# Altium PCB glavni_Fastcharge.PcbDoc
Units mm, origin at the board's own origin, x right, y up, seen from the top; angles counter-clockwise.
Board outline 90.02 x 90.02 mm, 2 copper layers (Top Layer, Bottom Layer); 0 components, 0 nets, 77 pads, 2 vias.
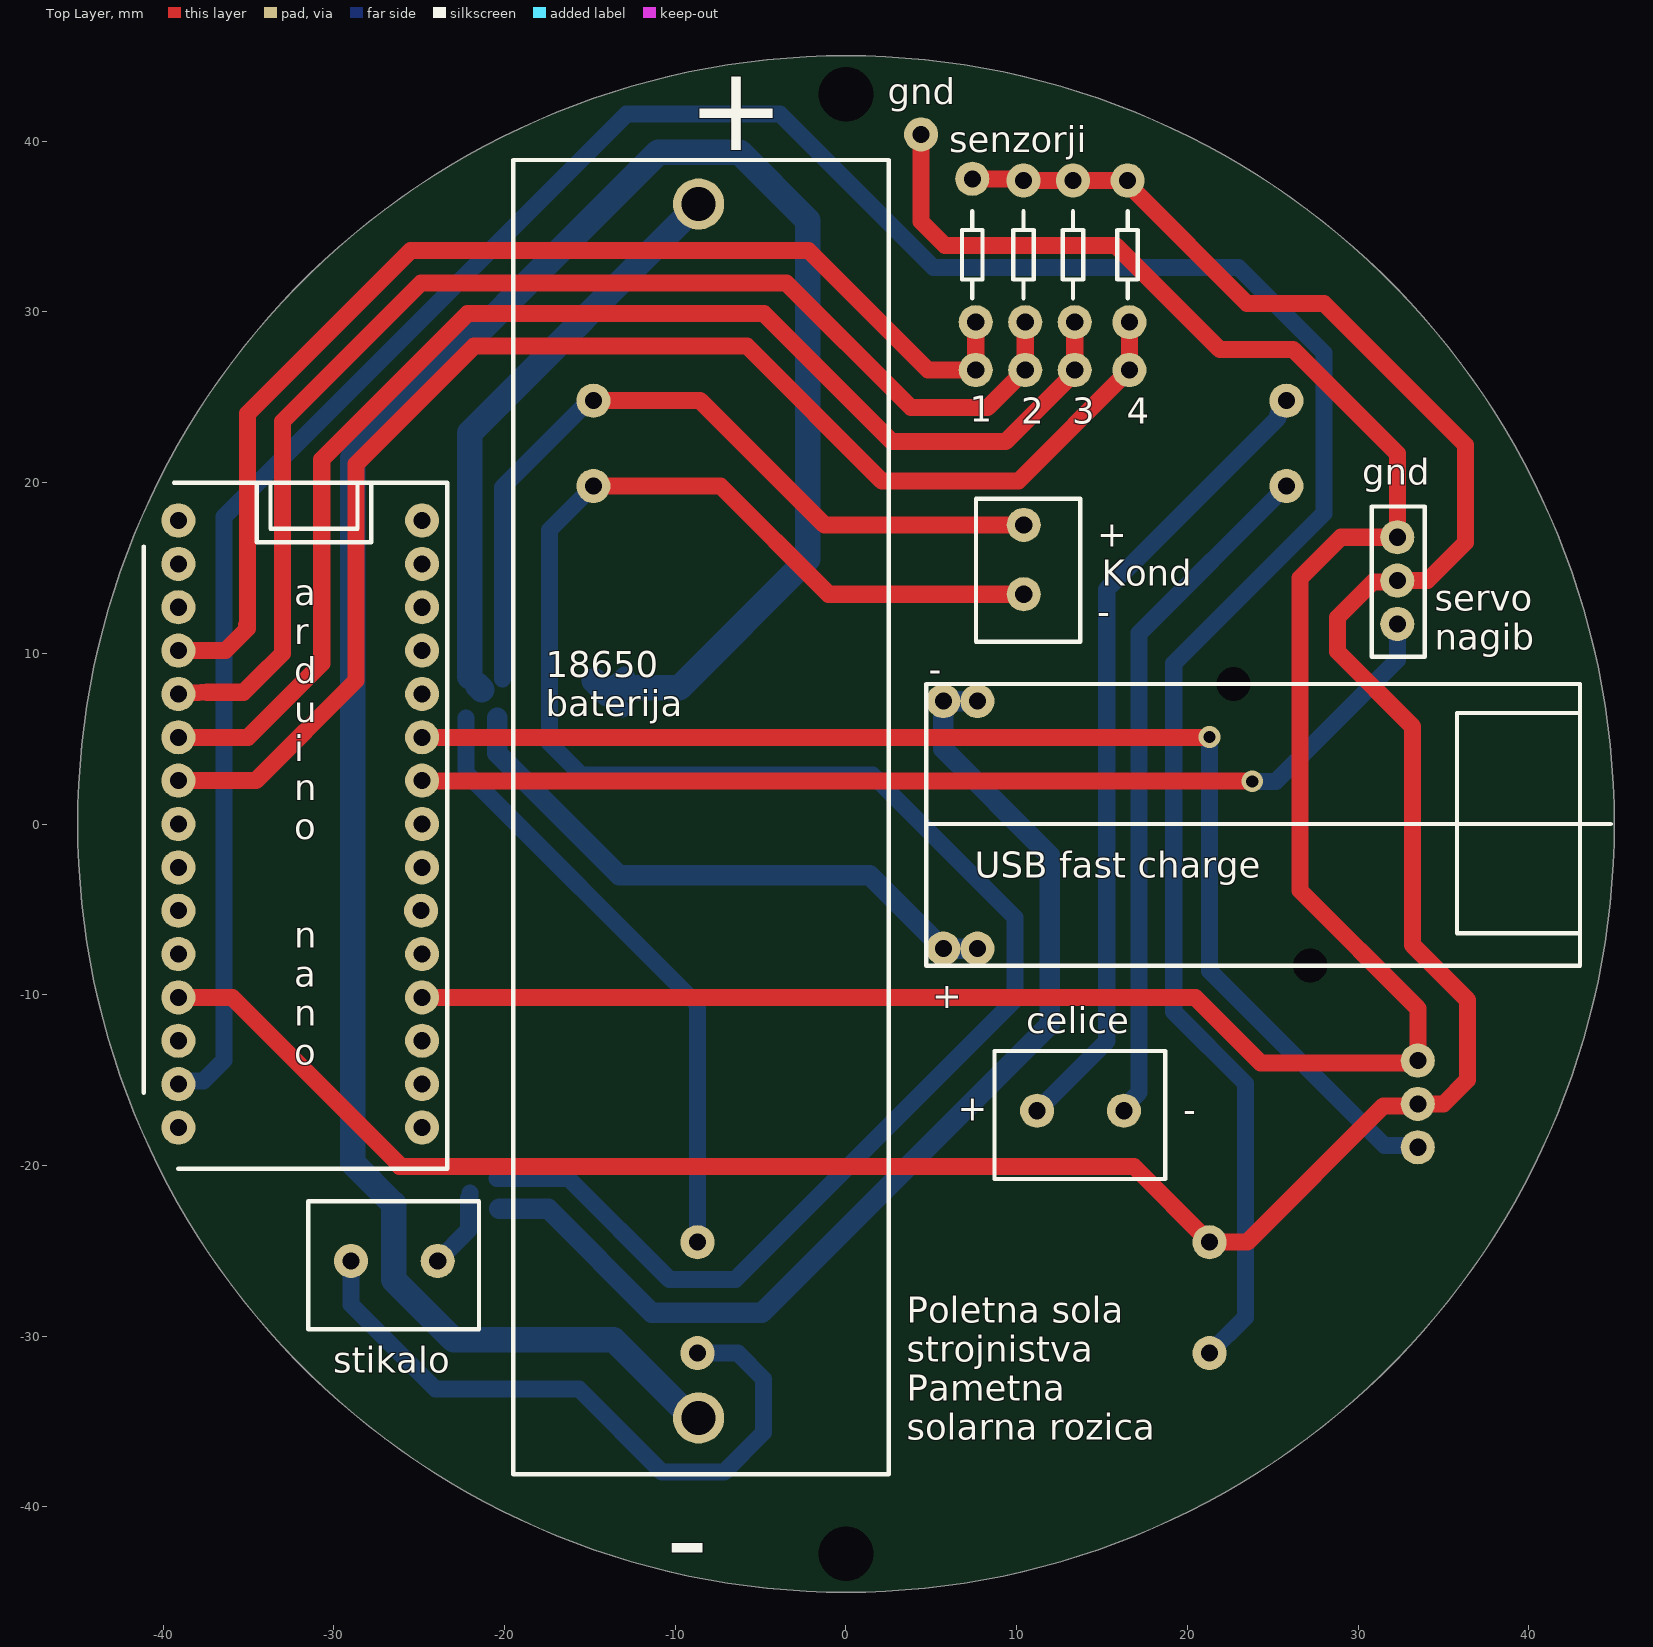
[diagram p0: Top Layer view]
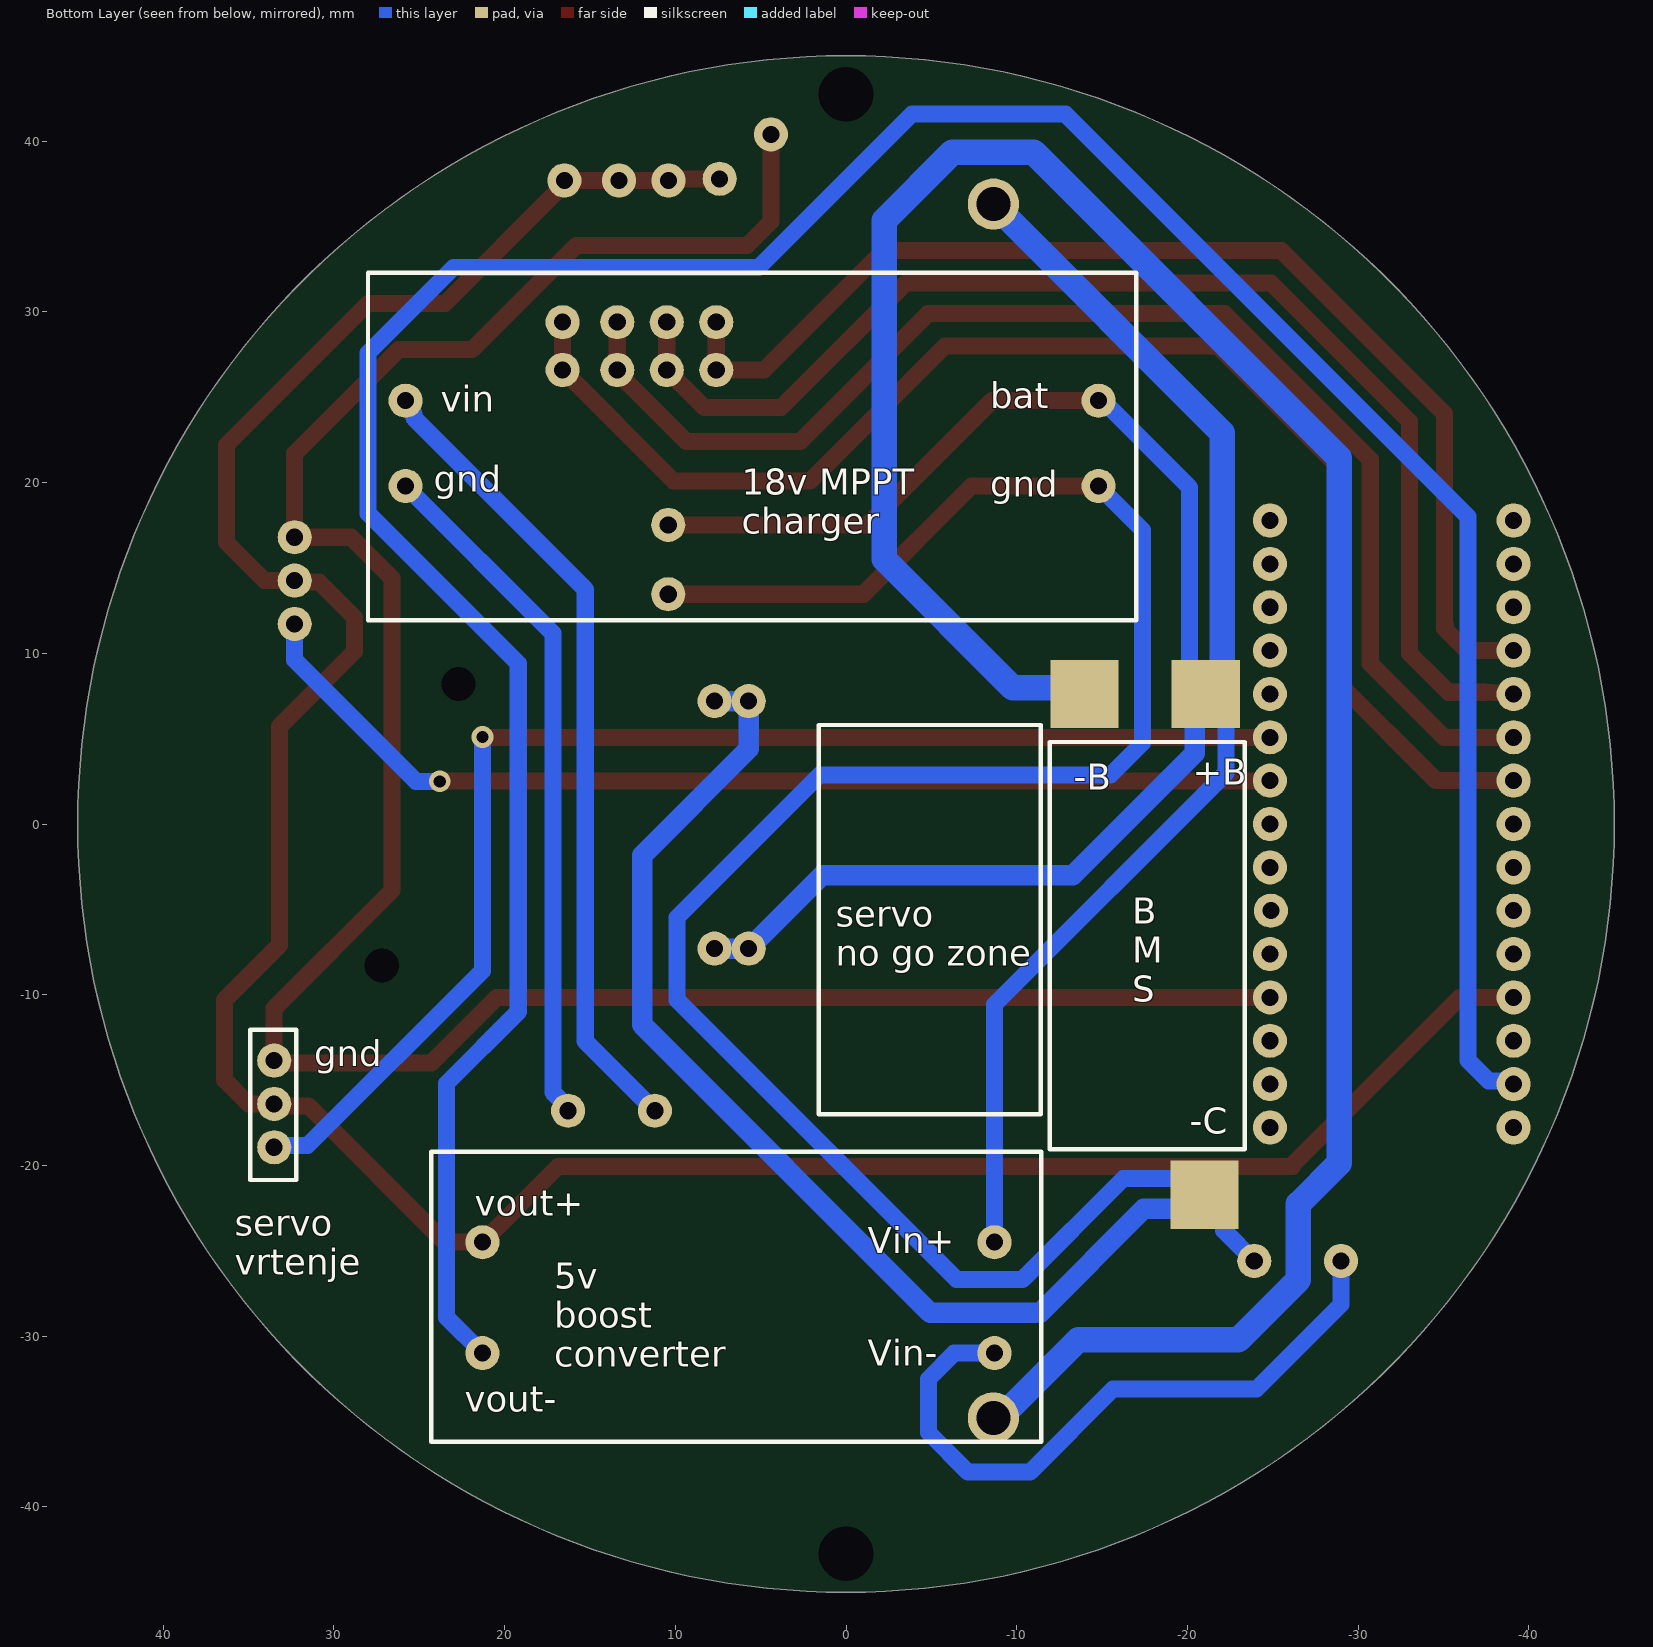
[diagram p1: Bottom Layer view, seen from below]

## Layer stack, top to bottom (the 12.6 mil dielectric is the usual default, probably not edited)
Top Solder: solder mask 0.0102, Solder Resist, Dk 3.5
Top Layer: signal copper 0.0356
Dielectric 1: dielectric 0.32, FR-4, Dk 4.8
Bottom Layer: signal copper 0.0356
Bottom Solder: solder mask 0.0102, Solder Resist, Dk 3.5

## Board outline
-45.011,0 ccw(c0,0) 0,-45.011 ccw(c0,0) 45.011,0 ccw(c0,0) 0,45.011 ccw(c0,0)

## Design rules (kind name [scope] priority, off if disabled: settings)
Clearance [All] p1: gap=0.254 ignorepadtopadclearanceinfootprint=FALSE except(0: Arc-Hole Track-Hole SMDPad-Hole THPad-Hole Via-Hole Fill-Hole Poly-Hole Region-Hole Text-Hole)
PolygonConnect [All] p1: connectstyle=Relief reliefconductorwidth=0.254 reliefentries=4 polygonreliefangle="90 Angle" airgapwidth=0.254
RoutingVias [All] p1: holewidth=0.711 width=1.27 viastyle="Through Hole" minholewidth=0.711 minwidth=1.27 maxholewidth=0.711 maxwidth=1.27
SolderMaskExpansion [All] p1: expansion=0.102 istentingtop=FALSE
Width [All] p1: maxlimit=1.5 minlimit=0.5 preferedwidth=1
30 further rules are at their usual default settings.

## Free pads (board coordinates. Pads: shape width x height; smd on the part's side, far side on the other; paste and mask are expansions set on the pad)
  round 2 hole 1: 105(-29,-25.6) 105(11.2,-16.8) 107(-23.92,-25.6) 107(16.28,-16.8) 129(25.8,24.8) 130(25.8,19.8) 131(-14.8,24.8) 132(-14.8,19.8) 137(-8.7,-24.5) 137(21.3,-24.5) 138(-8.7,-31) 138(21.3,-31) 141(-39.116,15.24) 141(-39.116,17.78) 141(-24.892,-5.08) 141(-24.836,-17.78) 141(-24.836,-15.24) 141(-24.836,-12.7) 141(-24.836,-10.16) 141(-24.836,-7.62) 141(-24.836,-2.54) 141(-24.836,0) 141(-24.836,2.54) 141(-24.836,5.08) 141(-24.836,7.62) 141(-24.836,10.16) 141(-24.836,12.7) 141(-24.836,15.24) 141(-24.836,17.78) 142(-39.116,12.7) 143(-39.116,10.16) 143(32.3,16.8) 143(33.5,-13.86) 144(-39.116,7.62) 144(32.3,14.26) 144(33.5,-16.4) 145(-39.116,5.08) 145(32.3,11.72) 145(33.5,-18.94) 146(-39.116,2.54) 147(-39.116,0) 148(-39.116,-2.54) 149(-39.116,-5.08) 150(-39.116,-7.62) 151(-39.116,-10.16) 152(-39.116,-12.7) 153(-39.116,-15.24) 154(-39.116,-17.78) 155(4.4,40.4) 156(7.6,26.6) 156(10.5,26.6) 156(13.4,26.6) 156(16.6,26.6) 157(7.6,29.4) 157(10.5,29.4) 157(13.4,29.4) 157(16.6,29.4) 158(7.4,37.8) 158(10.4,37.7) 158(10.414,13.462) 158(10.414,17.526) 158(13.3,37.7) 158(16.5,37.7) 169(5.7,-7.3) 169(5.7,7.2) 170(7.7,-7.3) 170(7.7,7.2)
  round 3 hole 2: 128(-8.636,36.322) ""(-8.636,-34.798)
  rect 4x4 smd far side: 134(-21.082,7.62) 134(-21,-21.725) 134(-13.97,7.62)
  round 1.524 hole 0.762: 141(-24.892,-5.08)
  round 2 hole 3.2: 155(0,-42.75) 155(0,42.75)
  round 1.524 hole 2: 171(27.2,-8.3) 172(22.7,8.2)

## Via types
v1: diameter 1.27, hole 0.711, Top Layer to Bottom Layer, 2 vias

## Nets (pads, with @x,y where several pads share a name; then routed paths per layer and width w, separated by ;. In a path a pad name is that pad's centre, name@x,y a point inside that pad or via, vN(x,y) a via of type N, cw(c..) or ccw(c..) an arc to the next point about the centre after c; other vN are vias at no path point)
copper on no net: | length 1541.1
  Top Layer w1: -39.116,-10.16 -35.956,-10.16 -26.116,-20 ; -39.116,2.54 -34.576,2.54 -28.702,8.414 -28.702,21.082 -21.784,28 -5.8,28 2.1,20.1 10.1,20.1 16.6,26.6 16.6,29.7 ; -39.116,5.08 -35.036,5.08 -30.716,9.4 -30.716,21.354 -22.17,29.9 -4.8,29.9 2.7,22.4 9.342,22.4 13.4,26.458 13.4,26.6 13.4,29.4 ; -39.116,7.62 -37.436,7.72 -35.296,7.72 -34.516,8.5 -33.02,9.996 -33.02,23.58 -24.9,31.7 -3.5,31.7 3.6,24.6 3.8,24.4 8.3,24.4 10.5,26.6 10.5,29.7 ; -39.116,10.16 -37.527,10.169 -36.347,10.169 -35.116,11.4 -35.116,11.646 ; -35.052,11.458 -35.052,24.048 -25.5,33.6 -2.2,33.6 4.8,26.6 7.6,26.6 7.6,29.4 ; -26.162,-20.066 16.866,-20.066 21.3,-24.5 23.506,-24.5 31.496,-16.51 33.782,-16.51 ; -24.836,2.54 -24.816,2.52 ; -23.82,-10.16 20.46,-10.16 24.3,-14 33.36,-14 33.5,-13.86 33.5,-10.8 26.6,-3.9 26.6,14.4 29,16.8 32.3,16.8 32.3,21.7 26.2,27.8 21.9,27.8 21.2,28.5 15.8,33.9 5.8,33.9 4.4,35.3 4.4,40.4 ; -23.82,5.08 21.28,5.08 v1(21.3,5.1) ; -23.8,2.52 23.78,2.52 v1(23.8,2.5) ; -14.8,19.8 -7.354,19.8 -1.016,13.462 10.414,13.462 ; -14.8,24.8 -8.544,24.8 -1.27,17.526 10.414,17.526 ; 7.4,29.3 7.6,29.1 ; 7.4,37.8 10.3,37.8 10.4,37.7 13.3,37.7 16.5,37.7 ; 13.2,29.3 13.4,29.1 ; 16.78,37.22 23.5,30.5 28,30.5 36.3,22.2 36.3,20.8 36.3,16.488 34.072,14.26 32.3,14.26 32.221,14.181 30.881,14.181 28.8,12.1 28.8,10.1 33.2,5.7 33.2,-7.1 36.4,-10.3 36.4,-15 35,-16.4 33.5,-16.4
  Bottom Layer w1: -39.116,-15.24 -38.925,-15.049 -37.655,-15.049 -36.449,-13.843 -36.449,-13.664 -36.449,18.001 -12.85,41.6 -3.875,41.6 5.125,32.6 23,32.6 28,27.6 28,18.2 19.2,9.4 19.2,-11 23.4,-15.2 23.4,-28.9 21.3,-31 ; -28.999,-25.601 -28.999,-28.151 -24.05,-33.1 -15.65,-33.1 -10.775,-37.975 -7.15,-37.975 -4.826,-35.651 -4.826,-32.512 -6.338,-31 -8.7,-31 ; -23.92,-25.6 -22.125,-23.805 -22.125,-21.925 -22.025,-21.825 -22.025,-21.625 ; -22.275,6.2 -22.275,3 -8.7,-10.575 -8.7,-12.3 -8.7,-24.5 ; -20.45,-20.775 -16.25,-20.775 -10.35,-26.675 -6.475,-26.675 9.9,-10.3 9.9,-5.475 1.55,2.875 -15.5,2.875 -17.375,4.75 -17.375,17.225 -14.85,19.75 -14.8,19.8 ; -20.125,8.5 -20.125,19.725 -15.05,24.8 -14.8,24.8 ; -13.97,7.62 -13.088,6.738 ; 11.2,-16.8 15.275,-12.725 15.275,13.751 25.3,23.776 25.3,24.029 25.8,24.529 25.8,24.8 ; 16.28,-16.8 16.28,-16.609 17.175,-15.714 17.175,11.175 25.8,19.8 ; v1(21.3,5.1) 21.3,-8.6 31.543,-18.843 33.403,-18.843 33.5,-18.94 ; v1(23.8,2.5) 25.2,2.5 32.3,9.6 32.3,11.72
  Bottom Layer w1.2: -20.425,6.225 -20.425,4.15 -13.275,-3 1.4,-3 5.7,-7.3 7.7,-7.3 ; -20.325,-22.55 -17.45,-22.55 -11.375,-28.625 -4.925,-28.625 11.925,-11.775 11.925,-1.825 5.7,4.4 5.7,7.2 7.7,7.2 ; -13.97,7.62 -12.954,8.636
  Bottom Layer w1.5: -22.05,8.625 -22.05,22.908 -8.636,36.322 ; -21.575,8.113 -21.336,7.874 ; -14.732,8.382 -13.97,7.62 ; -13.675,7.975 -9.775,7.975 -2.25,15.5 -2.25,35.375 -6.225,39.35 -11,39.35 -28.9,21.45 -28.9,-19.868 -26.506,-22.262 -26.506,-26.698 -22.978,-30.226 -13.599,-30.226 -9.027,-34.798 -8.636,-34.798

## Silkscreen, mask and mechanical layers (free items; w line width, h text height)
Top Overlay:
  lines w0.254: -41.148,-15.748 -41.148,16.256 ; -39.37,20 -23.368,20 -23.368,-20.2 -39.116,-20.2 ; -34.616,20 -34.516,20 -34.516,16.5 -27.816,16.5 -27.816,20 ; 4.7,-0.05 4.7,-8.3 43,-8.3 43,8.2 4.7,8.2 4.7,0 44.8,0 ; 7.4,30.8 7.4,31.9 ; 7.4,35.9 7.4,34.8 ; 10.4,30.8 10.4,31.9 ; 10.4,35.9 10.4,34.8 ; 13.3,30.8 13.3,31.9 ; 13.3,35.9 13.3,34.8 ; 16.5,30.8 16.5,31.9 ; 16.5,35.9 16.5,34.8 ; 30.8,18.6 30.8,9.8 33.9,9.8 33.9,18.6 30.9,18.6 ; -21.5,-29.6 -31.5,-29.6 -31.5,-22.1 -21.5,-22.1 ; -21.5,-29.6 -21.5,-22.1 ; -21.5,-29.6 -21.5,-22.1 ; 6.8,34.8 6.8,31.9 8,31.9 8,32.7 8,34.8 6.8,34.8 ; 6.8,34.8 7.4,34.8 ; 7.4,31.9 7.4,31.9 ; 7.4,34.8 7.4,34.8 ; 9.8,34.8 9.8,31.9 11,31.9 11,32.7 11,34.8 9.8,34.8 ; 9.8,34.8 10.4,34.8 ; 10.4,31.9 10.4,31.9 ; 10.4,34.8 10.4,34.8 ; 12.7,34.8 12.7,31.9 13.9,31.9 13.9,32.7 13.9,34.8 12.7,34.8 ; 12.7,34.8 13.3,34.8 ; 13.3,31.9 13.3,31.9 ; 13.3,34.8 13.3,34.8 ; 15.9,34.8 15.9,31.9 17.1,31.9 17.1,32.7 17.1,34.8 15.9,34.8 ; 15.9,34.8 16.5,34.8 ; 16.5,31.9 16.5,31.9 ; 16.5,34.8 16.5,34.8 ; 18.7,-20.8 18.7,-13.3 ; 18.7,-20.8 8.7,-20.8 8.7,-13.3 18.7,-13.3 ; 18.7,-20.8 18.7,-13.3 ; -33.716,17.3 -28.616,17.3 -28.616,20 -33.716,20 -33.716,17.3 ; -19.5,-38.1 2.5,-38.1 2.5,38.9 -19.5,38.9 -19.5,-38.1 ; 7.62,10.668 13.716,10.668 13.716,19.05 7.62,19.05 7.62,10.668 ; 35.8,-6.4 35.8,6.5 43,6.5 43,-6.4 35.8,-6.4
  text "gnd" at 2.454,42.162 h1.52
  text "+" at -9.3,39.475 h5
  text "senzorji" at 6.054,39.362 h1.52
  text "1" at 7.254,23.554 h1.52
  text "2" at 10.254,23.454 h1.52
  text "3" at 13.254,23.454 h1.52
  text "4" at 16.454,23.454 h1.52
  text "gnd" at 30.254,19.862 h1.52
  text "+" at 14.732,16.256 h1.52
  text "Kond" at 14.986,13.97 h1.52
  text "-" at 14.732,11.684 h1.52
  text "servo / nagib" at 34.5,10.2 h1.52
  text "-" at 4.854,8.292 h1.52
  text "18650 / baterija" at -17.6,6.3 h1.52
  text "a / r / d / u / i / n / o" at -32.316,-0.9 h1.52
  text "USB fast charge" at 7.554,-3.138 h1.52
  text "+" at 5.054,-10.8 h1.52
  text "celice" at 10.554,-12.246 h1.52
  text "n / a / n / o" at -32.316,-14.1 h1.52
  text "+" at 6.554,-17.4 h1.52
  text "-" at 19.754,-17.508 h1.52
  text "stikalo" at -30.046,-32.146 h1.52
  text "Poletna sola / strojnistva / Pametna / solarna rozica" at 3.556,-36.068 h1.52
  text "-" at -10.525,-44.3 h5
Bottom Overlay:
  lines w0.254: -23.368,-19.05 -21.55,-19.05 -11.938,-19.05 -11.938,4.8 -15.2,4.8 -23.368,4.8 -23.368,-19.05 ; -17,11.938 28,11.938 28,32.3 -17,32.3 -17,11.938 ; -11.43,-36.2 -11.43,-19.2 24.3,-19.2 24.3,-36.2 -11.43,-36.2 ; -11.4,-17 1.6,-17 1.6,5.8 -11.4,5.8 -11.4,0.5 -11.4,-17 ; 32.2,-20.86 34.9,-20.86 34.9,-12.06 32.2,-12.06 32.2,-20.86
  text "bat" at -8.454,24.354 h1.52
  text "vin" at 23.746,24.154 h1.52
  text "gnd" at 24.146,19.462 h1.52
  text "gnd" at -8.454,19.162 h1.52
  text "18v MPPT / charger" at 6.096,17.018 h1.52
  text "+B" at -20.304,2.304 h1.52
  text "-B" at -13.329,2.004 h1.52
  text "servo / no go zone" at 0.6,-8.3 h1.52
  text "B / M / S" at -16.764,-10.414 h1.52
  text "gnd" at 31.146,-14.198 h1.52
  text "-C" at -20.129,-18.146 h1.52
  text "vout+" at 21.746,-22.946 h1.52
  text "Vin+" at -1.27,-25.146 h1.52
  text "servo / vrtenje" at 35.8,-26.4 h1.52
  text "Vin-" at -1.27,-31.75 h1.52
  text "5v / boost / converter" at 17.1,-31.8 h1.52
  text "vout-" at 22.346,-34.446 h1.52
Mechanical 1:
  circle w0.1: c0,0 r45.011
